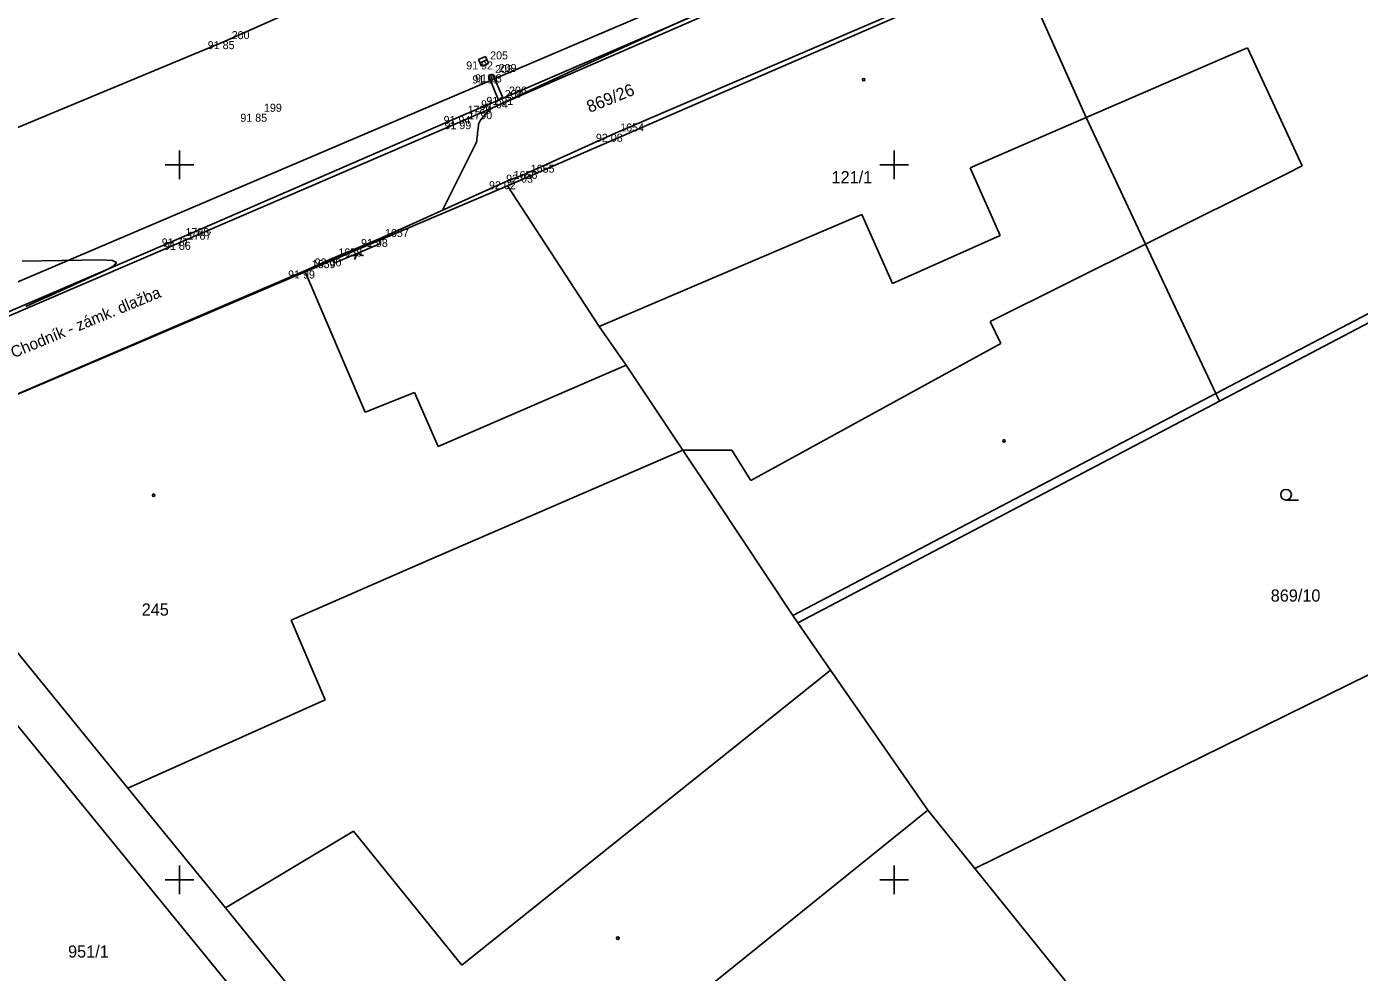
# Model space of a CAD drawing. Extents: x -711081 to -709338, y -1025122 to -1024092.
# Drawn here: x -710805.34 to -710758.72, y -1024978.24 to -1024945.16 of the extents above; entities that cross this region are included whole.
import ezdxf

# ---------------------------------------------------------------- set-up
doc = ezdxf.new("R2010")
doc.units = 0
for name, color, linetype in [('Ex_Major Contours', 7, 'Continuous'), ('Ex_Minor Contours', 7, 'Continuous'), ('Z_body', 7, 'Continuous'), ('Z_body_cisla', 7, 'Continuous'), ('Z_body_vysky_redukovane', 7, 'Continuous'), ('Z_budova', 7, 'Continuous'), ('Z_hektometricka_sit', 7, 'Continuous'), ('Z_katastr_cisla_pozemkova', 7, 'Continuous'), ('Z_katastr_cisla_stavebni', 7, 'Continuous'), ('Z_katastr_hranice', 7, 'Continuous'), ('Z_katastr_vnitrni_kresba', 7, 'Continuous'), ('Z_katastr_znacky_budov', 7, 'Continuous'), ('Z_katastr_znacky_kultur', 7, 'Continuous'), ('Z_komunikace', 7, 'Continuous'), ('Z_obruba', 7, 'Continuous'), ('Z_ploty', 7, 'Continuous'), ('Z_ploty_znacky', 7, 'Continuous'), ('Z_popisy', 7, 'Continuous'), ('Z_site_kanalizace_znaky', 7, 'Continuous'), ('Z_vdz12_prerusovana', 7, 'Continuous'), ('Z_vstupy', 7, 'Continuous'), ('Z_zlabek', 7, 'Continuous')]:
    doc.layers.add(name, color=color, linetype=linetype)

# ---------------------------------------------------------------- blocks, each defined once
blk = doc.blocks.new('POINT_DISPLAY')
blk.add_line((0, 0), (0, 0))
blk = doc.blocks.new('Z212')
for p, q in [((-0.17, 0.17), (0, 0)), ((0, 0), (0.17, 0.17))]:
    blk.add_line(p, q)
blk = doc.blocks.new('Z46260')
for p, q in [((0.13, 0.13), (-0.13, 0.13)), ((-0.13, 0.13), (-0.13, -0.13)), ((0.13, 0), (-0.13, 0)), ((0.13, -0.13), (0.13, 0.13)), ((-0.13, -0.13), (0.13, -0.13))]:
    blk.add_line(p, q)

msp = doc.modelspace()

# ---------------------------------------------------------------- linework, layer by layer
at = {"layer": 'Ex_Major Contours'}
msp.add_lwpolyline([(-710781.827, -1024944.696), (-710784.577, -1024945.937), (-710785.036, -1024946.145), (-710785.495, -1024946.354), (-710785.953, -1024946.565), (-710786.411, -1024946.777), (-710789.02, -1024947.987), (-710789.085, -1024948.022), (-710789.145, -1024948.064), (-710789.2, -1024948.112), (-710789.249, -1024948.167), (-710789.463, -1024948.436), (-710789.493, -1024948.479), (-710789.515, -1024948.524), (-710789.531, -1024948.573), (-710789.54, -1024948.624), (-710789.569, -1024948.88), (-710789.572, -1024948.909), (-710789.575, -1024948.938), (-710789.577, -1024948.967), (-710789.58, -1024948.996), (-710789.589, -1024949.112), (-710789.592, -1024949.141), (-710789.599, -1024949.169), (-710789.608, -1024949.196), (-710789.619, -1024949.222), (-710790.79, -1024951.58)], dxfattribs=at)
at = {"layer": 'Ex_Minor Contours'}
msp.add_lwpolyline([(-710805.495, -1024953.368), (-710802.725, -1024953.324), (-710802.345, -1024953.343), (-710802.204, -1024953.415), (-710802.301, -1024953.54), (-710802.637, -1024953.718), (-710804.457, -1024954.538), (-710804.912, -1024954.743), (-710805.367, -1024954.948)], dxfattribs=at)
at = {"layer": 'Z_budova'}
for p, q in [((-710774.32, -1024944.41), (-710784.8, -1024948.91)), ((-710787.94, -1024950.34), (-710788.54, -1024950.57)), ((-710795.59, -1024953.69), (-710809.21, -1024959.53))]:
    msp.add_line(p, q, dxfattribs=at)
at = {"layer": 'Z_hektometricka_sit'}
for p, q in [((-710800, -1024949.5), (-710800, -1024950.5)), ((-710775, -1024949.5), (-710775, -1024950.5)), ((-710800.5, -1024950), (-710799.5, -1024950)), ((-710775.5, -1024950), (-710774.5, -1024950)), ((-710800, -1024974.5), (-710800, -1024975.5)), ((-710775, -1024974.5), (-710775, -1024975.5)), ((-710800.5, -1024975), (-710799.5, -1024975)), ((-710775.5, -1024975), (-710774.5, -1024975))]:
    msp.add_line(p, q, dxfattribs=at)
at = {"layer": 'Z_katastr_hranice'}
for p, q in [((-710811.82, -1024956.71), (-710744.84, -1024928.18)), ((-710788.52, -1024950.73), (-710770.68, -1024942.98)), ((-710768.28, -1024948.34), (-710770.68, -1024942.98)), ((-710766.2, -1024952.77), (-710768.28, -1024948.34)), ((-710788.52, -1024950.73), (-710795.6, -1024953.74)), ((-710785.32, -1024955.65), (-710788.52, -1024950.73)), ((-710763.74, -1024957.99), (-710766.2, -1024952.77)), ((-710753.18, -1024952.78), (-710763.62, -1024958.26)), ((-710795.6, -1024953.74), (-710809.32, -1024959.57)), ((-710784.37, -1024957), (-710785.32, -1024955.65)), ((-710782.39, -1024959.98), (-710784.37, -1024957)), ((-710763.62, -1024958.26), (-710763.74, -1024957.99)), ((-710763.62, -1024958.26), (-710778.37, -1024966.01)), ((-710781.24, -1024961.7), (-710782.39, -1024959.98)), ((-710772.17, -1024974.6), (-710743.88, -1024960.68)), ((-710778.54, -1024965.76), (-710781.24, -1024961.7)), ((-710809.8, -1024961.98), (-710801.8, -1024971.8)), ((-710778.37, -1024966.01), (-710778.54, -1024965.76)), ((-710777.22, -1024967.67), (-710778.37, -1024966.01)), ((-710773.82, -1024972.56), (-710777.22, -1024967.67)), ((-710801.8, -1024971.8), (-710798.39, -1024975.98)), ((-710790.36, -1024985.88), (-710773.82, -1024972.56)), ((-710772.17, -1024974.6), (-710773.82, -1024972.56)), ((-710764.37, -1024984.27), (-710772.17, -1024974.6)), ((-710798.39, -1024975.98), (-710790.36, -1024985.88))]:
    msp.add_line(p, q, dxfattribs=at)
at = {"layer": 'Z_katastr_vnitrni_kresba'}
for p, q in [((-710763.24, -1024946.16), (-710762.64, -1024945.9)), ((-710760.72, -1024950.03), (-710762.64, -1024945.9)), ((-710768.28, -1024948.34), (-710763.24, -1024946.16)), ((-710772.34, -1024950.1), (-710768.28, -1024948.34)), ((-710771.29, -1024952.47), (-710772.34, -1024950.1)), ((-710761.29, -1024950.32), (-710760.72, -1024950.03)), ((-710766.2, -1024952.77), (-710761.29, -1024950.32)), ((-710785.32, -1024955.65), (-710776.13, -1024951.73)), ((-710776.13, -1024951.73), (-710775.05, -1024954.15)), ((-710775.05, -1024954.15), (-710771.29, -1024952.47)), ((-710766.2, -1024952.77), (-710771.64, -1024955.48)), ((-710763.74, -1024957.99), (-710753.32, -1024952.52)), ((-710795.6, -1024953.74), (-710793.5, -1024958.64)), ((-710771.64, -1024955.48), (-710771.26, -1024956.25)), ((-710771.26, -1024956.25), (-710780.01, -1024961.03)), ((-710790.95, -1024959.85), (-710784.37, -1024957)), ((-710793.5, -1024958.64), (-710791.78, -1024957.96)), ((-710791.78, -1024957.96), (-710790.95, -1024959.85)), ((-710778.54, -1024965.76), (-710763.74, -1024957.99)), ((-710782.39, -1024959.98), (-710791.28, -1024963.82)), ((-710780.67, -1024959.98), (-710782.39, -1024959.98)), ((-710780.01, -1024961.03), (-710780.67, -1024959.98)), ((-710812.5, -1024961.25), (-710775.327, -1025006.719)), ((-710791.28, -1024963.82), (-710796.09, -1024965.92)), ((-710796.09, -1024965.92), (-710794.9, -1024968.71)), ((-710790.12, -1024977.99), (-710777.22, -1024967.67)), ((-710794.9, -1024968.71), (-710801.8, -1024971.8)), ((-710798.39, -1024975.98), (-710793.91, -1024973.3)), ((-710793.91, -1024973.3), (-710790.12, -1024977.99))]:
    msp.add_line(p, q, dxfattribs=at)
at = {"layer": 'Z_katastr_znacky_budov'}
for centre in [(-710776.062, -1024947.02), (-710771.152, -1024959.65), (-710800.902, -1024961.55), (-710784.662, -1024977.04)]:
    msp.add_circle(centre, 0.0437, dxfattribs=at)
at = {"layer": 'Z_katastr_znacky_kultur'}
msp.add_line((-710761.288, -1024961.72), (-710760.851, -1024961.72), dxfattribs=at)
msp.add_circle((-710761.288, -1024961.532), 0.187, dxfattribs=at)
at = {"layer": 'Z_komunikace'}
for p, q in [((-710788.84, -1024947.74), (-710780.55, -1024944.14)), ((-710790.15, -1024948.29), (-710788.84, -1024947.74)), ((-710800.01, -1024952.57), (-710790.15, -1024948.29)), ((-710810.31, -1024957), (-710800.01, -1024952.57))]:
    msp.add_line(p, q, dxfattribs=at)
at = {"layer": 'Z_obruba'}
for p, q in [((-710790.12, -1024948.47), (-710780.48, -1024944.27)), ((-710799.93, -1024952.69), (-710790.12, -1024948.47)), ((-710810.28, -1024957.14), (-710799.93, -1024952.69))]:
    msp.add_line(p, q, dxfattribs=at)
at = {"layer": 'Z_ploty'}
for p, q in [((-710793.04, -1024952.59), (-710794.66, -1024953.27)), ((-710792.97, -1024952.75), (-710794.59, -1024953.43)), ((-710793.04, -1024952.59), (-710792.97, -1024952.75)), ((-710794.66, -1024953.27), (-710794.59, -1024953.43))]:
    msp.add_line(p, q, dxfattribs=at)
at = {"layer": 'Z_vdz12_prerusovana'}
for p, q in [((-710798.4, -1024945.67), (-710786.68, -1024940.44)), ((-710810.93, -1024950.88), (-710798.4, -1024945.67))]:
    msp.add_line(p, q, dxfattribs=at)
at = {"layer": 'Z_vstupy'}
for p, q in [((-710787.94, -1024950.34), (-710784.8, -1024948.91)), ((-710793.04, -1024952.59), (-710788.54, -1024950.57)), ((-710795.59, -1024953.69), (-710794.66, -1024953.27))]:
    msp.add_line(p, q, dxfattribs=at)
at = {"layer": 'Z_zlabek'}
for p, q in [((-710789.19, -1024946.87), (-710789.05, -1024946.83)), ((-710789.05, -1024946.83), (-710788.7, -1024947.62)), ((-710788.84, -1024947.74), (-710789.19, -1024946.87)), ((-710788.7, -1024947.62), (-710788.84, -1024947.74))]:
    msp.add_line(p, q, dxfattribs=at)

# ---------------------------------------------------------------- block references
at = {"layer": 'Z_body'}
for p in [(-710798.4, -1024945.67), (-710789.36, -1024946.38), (-710789.05, -1024946.83), (-710789.19, -1024946.87), (-710788.84, -1024947.74), (-710788.7, -1024947.62), (-710797.26, -1024948.21), (-710790.15, -1024948.29), (-710790.12, -1024948.47), (-710784.8, -1024948.91), (-710788.54, -1024950.57), (-710787.94, -1024950.34), (-710800.01, -1024952.57), (-710799.93, -1024952.69), (-710793.04, -1024952.59), (-710794.66, -1024953.27), (-710795.59, -1024953.69)]:
    msp.add_blockref('POINT_DISPLAY', p, dxfattribs=at)
at = {"layer": 'Z_ploty_znacky', "rotation": -157.20000000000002}
msp.add_blockref('Z212', (-710793.78, -1024953.09), dxfattribs=at)
at = {"layer": 'Z_site_kanalizace_znaky', "rotation": 23.399999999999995}
msp.add_blockref('Z46260', (-710789.36, -1024946.38), dxfattribs=at)

# ---------------------------------------------------------------- texts
at = {"layer": 'Z_body_cisla'}
for s, p in [('200', (-710798.17, -1024945.6)), ('205', (-710789.13, -1024946.31)), ('208', (-710788.96, -1024946.79)), ('209', (-710788.83, -1024946.75)), ('206', (-710788.47, -1024947.54)), ('207', (-710788.62, -1024947.66)), ('199', (-710797.04, -1024948.14)), ('1789', (-710789.92, -1024948.21)), ('1790', (-710789.89, -1024948.4)), ('1654', (-710784.58, -1024948.83)), ('1655', (-710787.71, -1024950.27)), ('1656', (-710788.31, -1024950.49)), ('1788', (-710799.79, -1024952.49)), ('1787', (-710799.71, -1024952.61)), ('1657', (-710792.81, -1024952.52)), ('1659', (-710795.37, -1024953.61)), ('1658', (-710794.44, -1024953.2))]:
    msp.add_text(s, height=0.28, dxfattribs=at).set_placement(p)
at = {"layer": 'Z_body_vysky_redukovane'}
for s, p in [('91 85', (-710799.007, -1024945.95)), ('91 92', (-710789.967, -1024946.66)), ('91 93', (-710789.657, -1024947.11)), ('91 91', (-710789.75, -1024947.15)), ('91 94', (-710789.447, -1024948.02)), ('91 91', (-710789.26, -1024947.9)), ('91 85', (-710797.867, -1024948.49)), ('91 94', (-710790.757, -1024948.57)), ('91 99', (-710790.727, -1024948.75)), ('92 08', (-710785.43, -1024949.19)), ('92 02', (-710789.17, -1024950.85)), ('92 03', (-710788.57, -1024950.62)), ('91 77', (-710800.617, -1024952.85)), ('91 86', (-710800.537, -1024952.97)), ('91 98', (-710793.647, -1024952.87)), ('92 00', (-710795.267, -1024953.55)), ('91 99', (-710796.197, -1024953.97))]:
    msp.add_text(s, height=0.28, dxfattribs=at).set_placement(p)
at = {"layer": 'Z_katastr_cisla_pozemkova'}
msp.add_text('869/26', height=0.425, rotation=22, dxfattribs=at).set_placement((-710785.65, -1024948.183))
for s, p in [('869/10', (-710761.824, -1024965.27)), ('951/1', (-710803.893, -1024977.72))]:
    msp.add_text(s, height=0.425, dxfattribs=at).set_placement(p)
at = {"layer": 'Z_katastr_cisla_stavebni'}
for s, p in [('121/1', (-710777.186, -1024950.64)), ('245', (-710801.318, -1024965.76))]:
    msp.add_text(s, height=0.425, dxfattribs=at).set_placement(p)
at = {"layer": 'Z_popisy'}
msp.add_text('Chodník - zámk. dlažba', height=0.4, rotation=22.5, dxfattribs=at).set_placement((-710805.8, -1024956.76))

doc.saveas('drawing.dxf')
